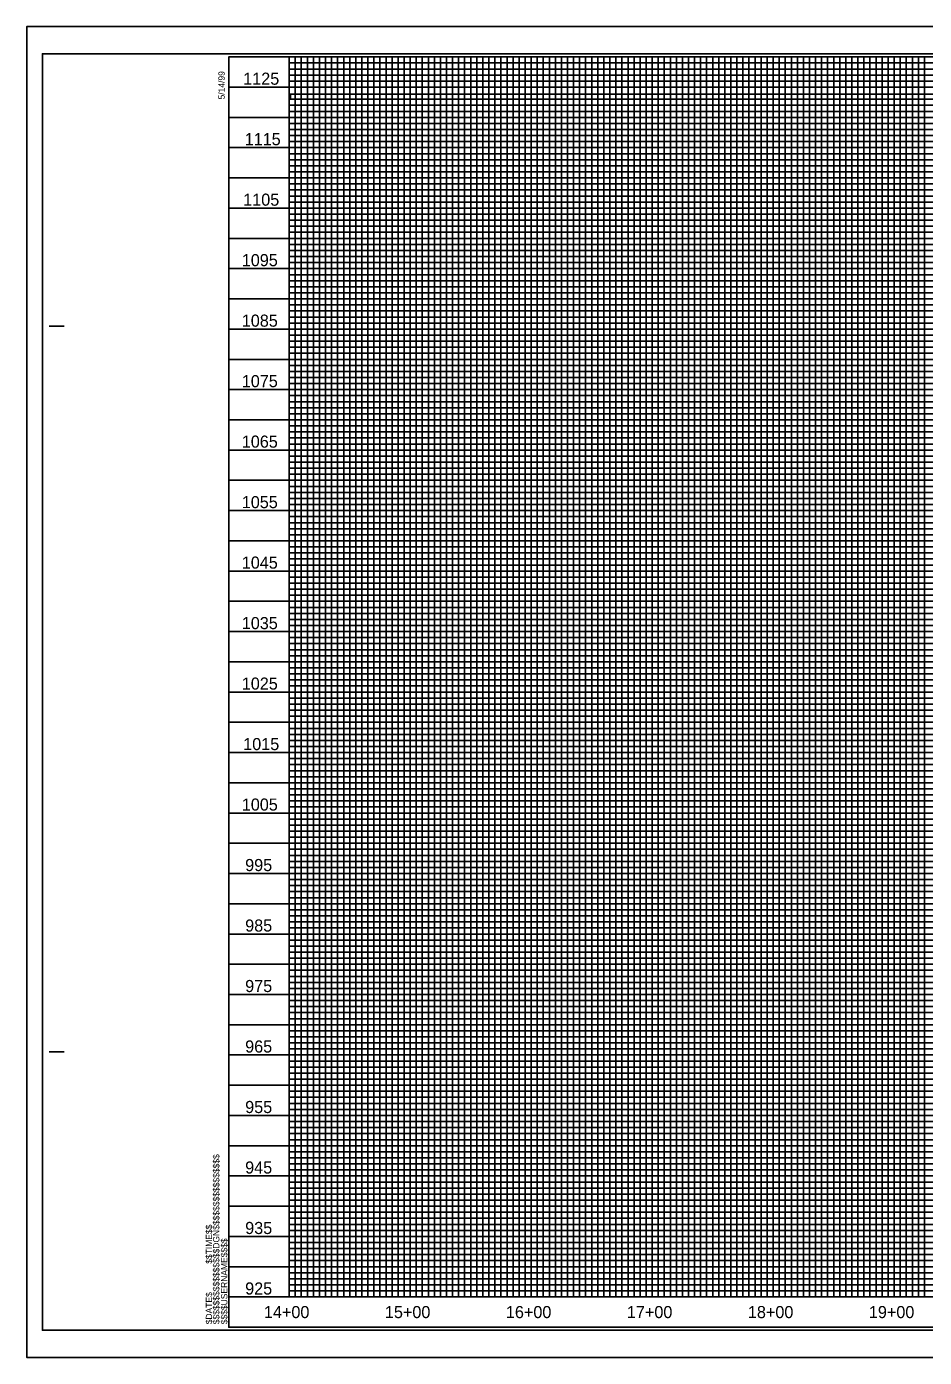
# Model space of a CAD drawing. Extents: x 1260839 to 1262605, y 747346 to 748446.
# Drawn here: x 1260839 to 1261581, y 747346 to 748446 of the extents above; entities that cross this region are included whole.
import ezdxf

# ---------------------------------------------------------------- set-up
doc = ezdxf.new("R2010")
doc.units = 0
for name, color, linetype in [('Pattern 1', 7, 'Continuous'), ('Pattern 2', 7, 'Continuous'), ('Prop Drainage Structure Bridge Opening', 7, 'Continuous'), ('Prop Grid Mask', 7, 'Continuous'), ('Prop Horizontal Alignment Curve and Spiral Data', 7, 'Continuous'), ('Prop Paved Shoulder', 7, 'Continuous'), ('Prop PFL Text', 7, 'Continuous'), ('Prop Roadway Bridge', 7, 'Continuous'), ('Prop Terminator CELL', 7, 'Continuous'), ('Prop Vertical Profile Strip Grade', 7, 'Continuous'), ('Prop VPI Label', 7, 'Continuous'), ('Sheet Sticker Exception Certification CELL', 7, 'Continuous')]:
    doc.layers.add(name, color=color, linetype=linetype)

msp = doc.modelspace()

# ---------------------------------------------------------------- linework, layer by layer
at = {"layer": 'Pattern 1'}
for points in [[(1261005.8, 748420.7), (1261055.8, 748420.7), (1261055.8, 747395.7), (1261105.8, 747395.7), (1261105.8, 748420.7), (1261155.8, 748420.7), (1261155.8, 747395.7), (1261205.8, 747395.7), (1261205.8, 748420.7), (1261255.8, 748420.7), (1261255.8, 747395.7), (1261305.8, 747395.7), (1261305.8, 748420.7), (1261355.8, 748420.7), (1261355.8, 747395.7), (1261405.8, 747395.7), (1261405.8, 748420.7), (1261455.8, 748420.7), (1261455.8, 747395.7), (1261505.8, 747395.7), (1261505.8, 748420.7), (1261555.8, 748420.7), (1261555.8, 747395.7), (1261605.8, 747395.7)], [(1262305.7, 748345.7), (1261005.9, 748345.7), (1261005.9, 748395.7), (1262205.8, 748395.7)], [(1262505.8, 748245.7), (1261005.8, 748245.7), (1261005.8, 748295.7), (1262305.7, 748295.7)], [(1262505.8, 748145.7), (1261005.8, 748145.7), (1261005.8, 748195.7), (1262505.8, 748195.7)], [(1262505.8, 748045.7), (1261005.8, 748045.7), (1261005.8, 748095.7), (1262505.8, 748095.7)], [(1262505.8, 747945.7), (1261005.8, 747945.7), (1261005.8, 747995.7), (1262505.8, 747995.7)], [(1262505.8, 747845.7), (1261005.8, 747845.7), (1261005.8, 747895.7), (1262505.8, 747895.7)], [(1262505.8, 747745.7), (1261005.8, 747745.7), (1261005.8, 747795.7), (1262505.8, 747795.7)], [(1262505.8, 747645.7), (1261005.8, 747645.7), (1261005.8, 747695.7), (1262505.8, 747695.7)], [(1262505.8, 747545.7), (1261005.8, 747545.7), (1261005.8, 747595.7), (1262505.8, 747595.7)], [(1262505.8, 747445.7), (1261005.8, 747445.7), (1261005.8, 747495.7), (1262505.8, 747495.7)]]:
    msp.add_lwpolyline(points, dxfattribs=at)
at = {"layer": 'Pattern 2'}
for points in [[(1261080.8, 747395.7), (1261080.8, 748420.7), (1261130.8, 748420.7), (1261130.8, 747395.7), (1261180.8, 747395.7), (1261180.8, 748420.7), (1261230.8, 748420.7), (1261230.8, 747395.7), (1261280.8, 747395.7), (1261280.8, 748420.7), (1261330.8, 748420.7), (1261330.8, 747395.7), (1261380.8, 747395.7), (1261380.8, 748420.7), (1261430.8, 748420.7), (1261430.8, 747395.7), (1261480.8, 747395.7), (1261480.8, 748420.7), (1261530.8, 748420.7), (1261530.8, 747395.7), (1261580.8, 747395.7), (1261580.8, 748420.7), (1261630.8, 748420.7)], [(1261005.8, 748370.7), (1262305.7, 748370.7)], [(1262305.7, 748320.7), (1261005.8, 748320.7), (1261005.8, 748270.7), (1262305.7, 748270.7)], [(1262505.8, 748220.7), (1261005.8, 748220.7), (1261005.8, 748170.7), (1262505.8, 748170.7)], [(1262505.8, 748120.7), (1261005.8, 748120.7), (1261005.8, 748070.7), (1262505.8, 748070.7)], [(1262505.8, 748020.7), (1261005.8, 748020.7), (1261005.8, 747970.7), (1262505.8, 747970.7)], [(1262505.8, 747920.7), (1261005.8, 747920.7), (1261005.8, 747870.7), (1262505.8, 747870.7)], [(1262505.8, 747820.7), (1261005.8, 747820.7), (1261005.8, 747770.7), (1262505.8, 747770.7)], [(1262505.8, 747720.7), (1261005.8, 747720.7), (1261005.8, 747670.7), (1262505.8, 747670.7)], [(1262505.8, 747620.7), (1261005.8, 747620.7), (1261005.8, 747570.7), (1262505.8, 747570.7)], [(1262505.8, 747520.7), (1261005.8, 747520.7), (1261005.8, 747470.7), (1262505.8, 747470.7)], [(1262505.8, 747420.7), (1261005.8, 747420.7)]]:
    msp.add_lwpolyline(points, dxfattribs=at)
at = {"layer": 'Prop Drainage Structure Bridge Opening'}
for p, q in [((1262522.8, 748445.7), (1260838.8, 748445.7)), ((1260838.8, 748445.7), (1260838.8, 747345.7)), ((1260838.8, 747345.7), (1262522.8, 747345.7))]:
    msp.add_line(p, q, dxfattribs=at)
at = {"layer": 'Prop Grid Mask'}
msp.add_lwpolyline([(1262455.8, 748259.7), (1262455.8, 747395.7), (1261055.8, 747395.7), (1261055.8, 748420.7), (1262305.7, 748420.7), (1262305.7, 748259.7)], close=True, dxfattribs=at)
at = {"layer": 'Prop Paved Shoulder'}
for p, q in [((1260857.3, 748198.2), (1260869.8, 748198.2)), ((1260857.3, 747598.2), (1260869.8, 747598.2)), ((1262505.8, 747395.7), (1261005.8, 747395.7)), ((1261005.8, 747370.7), (1261005.8, 747370.7)), ((1261005.8, 747370.7), (1261005.8, 747370.7)), ((1261005.8, 747370.7), (1261005.8, 747370.7)), ((1261005.8, 747370.7), (1261005.8, 747370.7)), ((1261005.8, 747370.7), (1261005.8, 747370.7)), ((1261005.8, 747370.7), (1261005.8, 747370.7))]:
    msp.add_line(p, q, dxfattribs=at)
msp.add_lwpolyline([(1262505.8, 748420.7), (1261005.8, 748420.7), (1261005.8, 747370.7), (1262505.8, 747370.7)], close=True, dxfattribs=at)
msp.add_lwpolyline([(1261043.3, 747370.7), (1261043.3, 747370.7)], dxfattribs=at)
at = {"layer": 'Prop PFL Text'}
for p, q in [((1261055.8, 748420.7), (1261055.8, 747395.7)), ((1261105.8, 748420.7), (1261105.8, 747395.7)), ((1261155.8, 748420.7), (1261155.8, 747395.7)), ((1261205.8, 748420.7), (1261205.8, 747395.7)), ((1261255.8, 748420.7), (1261255.8, 747395.7)), ((1261305.8, 748420.7), (1261305.8, 747395.7)), ((1261355.8, 748420.7), (1261355.8, 747395.7)), ((1261405.8, 748420.7), (1261405.8, 747395.7)), ((1261455.8, 748420.7), (1261455.8, 747395.7)), ((1261505.8, 748420.7), (1261505.8, 747395.7)), ((1261555.8, 748420.7), (1261555.8, 747395.7)), ((1261005.8, 748395.7), (1262205.8, 748395.7)), ((1261005.8, 748345.7), (1262305.7, 748345.7)), ((1261005.8, 748295.7), (1262305.7, 748295.7)), ((1261005.8, 748245.7), (1262505.8, 748245.7)), ((1261005.8, 748195.7), (1262505.8, 748195.7)), ((1261005.8, 748145.7), (1262505.8, 748145.7)), ((1261005.8, 748095.7), (1262505.8, 748095.7)), ((1261005.8, 748045.7), (1262505.8, 748045.7)), ((1261005.8, 747995.7), (1262505.8, 747995.7)), ((1261005.8, 747945.7), (1262505.8, 747945.7)), ((1261005.8, 747895.7), (1262505.8, 747895.7)), ((1261005.8, 747845.7), (1262505.8, 747845.7)), ((1261005.8, 747795.7), (1262505.8, 747795.7)), ((1261005.8, 747745.7), (1262505.8, 747745.7)), ((1261005.8, 747695.7), (1262505.8, 747695.7)), ((1261005.8, 747645.7), (1262505.8, 747645.7)), ((1261005.8, 747595.7), (1262505.8, 747595.7)), ((1261005.8, 747545.7), (1262505.8, 747545.7)), ((1261005.8, 747495.7), (1262505.8, 747495.7)), ((1261005.8, 747445.7), (1262505.8, 747445.7))]:
    msp.add_line(p, q, dxfattribs=at)
at = {"layer": 'Prop Roadway Bridge'}
msp.add_line((1261005.8, 747370.7), (1261005.8, 747370.7), dxfattribs=at)
at = {"layer": 'Prop Terminator CELL'}
msp.add_lwpolyline([(1262518.3, 748423.3), (1260851.8, 748423.3), (1260851.8, 747368.2), (1262518.3, 747368.2)], close=True, dxfattribs=at)
at = {"layer": 'Prop VPI Label'}
msp.add_lwpolyline([(1262522.8, 748445.7), (1260838.8, 748445.7), (1260838.8, 747345.7), (1262522.8, 747345.7)], close=True, dxfattribs=at)
at = {"layer": 'Sheet Sticker Exception Certification CELL'}
for p, q in [((1262455.8, 748240.7), (1261055.8, 748240.7)), ((1261055.8, 748240.7), (1261055.8, 748235.7)), ((1261055.8, 748235.7), (1262455.8, 748235.7)), ((1262455.8, 748215.7), (1261055.8, 748215.7))]:
    msp.add_line(p, q, dxfattribs=at)
for points in [[(1261060.8, 748420.7), (1261065.8, 748420.7), (1261070.8, 748420.7), (1261075.8, 748420.7), (1261085.8, 748420.7), (1261052.7, 748420.7), (1261057.7, 748420.7), (1261015.8, 748420.7), (1261020.8, 748420.7), (1261025.8, 748420.7), (1261035.8, 748420.7), (1261040.8, 748420.7), (1261045.8, 748420.7), (1261050.8, 748420.7), (1261060.8, 748420.7), (1261060.8, 747395.7), (1261065.8, 747395.7), (1261065.8, 748420.7), (1261070.8, 748420.7), (1261070.8, 747395.7), (1261075.8, 747395.7), (1261075.8, 748420.7), (1261085.8, 748420.7), (1261085.8, 747395.7), (1261090.8, 747395.7), (1261090.8, 748420.7), (1261095.8, 748420.7), (1261095.8, 747395.7), (1261100.8, 747395.7), (1261100.8, 748420.7), (1261110.8, 748420.7), (1261110.8, 747395.7), (1261115.8, 747395.7), (1261115.8, 748420.7), (1261120.8, 748420.7), (1261120.8, 747395.7), (1261125.8, 747395.7), (1261125.8, 748420.7), (1261135.8, 748420.7), (1261135.8, 747395.7), (1261140.8, 747395.7), (1261140.8, 748420.7), (1261145.8, 748420.7), (1261145.8, 747395.7), (1261150.8, 747395.7), (1261150.8, 748420.7), (1261160.8, 748420.7), (1261160.8, 747395.7), (1261165.8, 747395.7), (1261165.8, 748420.7), (1261170.8, 748420.7), (1261170.8, 747395.7), (1261175.8, 747395.7), (1261175.8, 748420.7), (1261185.8, 748420.7), (1261185.8, 747395.7), (1261190.8, 747395.7), (1261190.8, 748420.7), (1261195.8, 748420.7), (1261195.8, 747395.7), (1261200.8, 747395.7), (1261200.8, 748420.7), (1261210.8, 748420.7), (1261210.8, 747395.7), (1261215.8, 747395.7), (1261215.8, 748420.7), (1261220.8, 748420.7), (1261220.8, 747395.7)], [(1261220.8, 747395.7), (1261225.8, 747395.7), (1261225.8, 748420.7), (1261235.8, 748420.7), (1261235.8, 747395.7), (1261240.8, 747395.7), (1261240.8, 748420.7), (1261245.8, 748420.7), (1261245.8, 747395.7), (1261250.8, 747395.7), (1261250.8, 748420.7), (1261260.8, 748420.7), (1261260.8, 747395.7), (1261265.8, 747395.7), (1261265.8, 748420.7), (1261265.8, 748420.7), (1261270.8, 748420.7), (1261270.8, 747395.7), (1261275.8, 747395.7), (1261275.8, 748420.7), (1261285.8, 748420.7), (1261285.8, 747395.7), (1261290.8, 747395.7), (1261290.8, 748420.7), (1261295.8, 748420.7), (1261295.8, 747395.7), (1261300.8, 747395.7), (1261300.8, 748420.7), (1261310.8, 748420.7), (1261310.8, 747395.7), (1261315.8, 747395.7), (1261315.8, 748420.7), (1261320.8, 748420.7), (1261320.8, 747395.7), (1261325.8, 747395.7), (1261325.8, 748420.7), (1261335.8, 748420.7), (1261335.8, 747395.7), (1261340.8, 747395.7), (1261340.8, 748420.7), (1261345.8, 748420.7), (1261345.8, 747395.7), (1261350.8, 747395.7), (1261350.8, 748420.7), (1261360.8, 748420.7), (1261360.8, 747395.7), (1261365.8, 747395.7), (1261365.8, 748420.7), (1261370.8, 748420.7), (1261370.8, 747395.7), (1261375.8, 747395.7), (1261375.8, 748420.7), (1261385.8, 748420.7), (1261385.8, 747395.7), (1261400.8, 747395.7), (1261400.8, 748420.7), (1261410.8, 748420.7), (1261410.8, 747395.7), (1261415.8, 747395.7), (1261415.8, 748420.7), (1261420.8, 748420.7), (1261420.8, 747395.7), (1261425.8, 747395.7), (1261425.8, 748420.7), (1261435.8, 748420.7), (1261435.8, 747395.7), (1261440.8, 747395.7), (1261440.8, 748420.7), (1261445.8, 748420.7), (1261445.8, 747395.7), (1261450.8, 747395.7), (1261450.8, 748420.7), (1261460.8, 748420.7), (1261460.8, 747395.7), (1261465.8, 747395.7), (1261465.8, 748420.7), (1261470.8, 748420.7), (1261470.8, 747395.7), (1261475.8, 747395.7), (1261475.8, 748420.7), (1261485.8, 748420.7), (1261485.8, 747395.7), (1261490.8, 747395.7), (1261490.8, 748420.7), (1261495.8, 748420.7), (1261495.8, 747395.7), (1261500.8, 747395.7), (1261500.8, 748420.7), (1261510.8, 748420.7), (1261510.8, 747395.7), (1261515.8, 747395.7), (1261515.8, 748420.7), (1261520.8, 748420.7), (1261520.8, 747395.7), (1261525.8, 747395.7), (1261525.8, 748420.7), (1261535.8, 748420.7), (1261535.8, 747395.7)], [(1261390.8, 748420.7), (1261390.8, 747395.7), (1261395.8, 747395.7), (1261395.8, 748420.7)], [(1261390.8, 748420.1), (1261390.8, 747395.7), (1261395.8, 747395.7), (1261395.8, 748420.1)], [(1261540.8, 748420.7), (1261540.8, 747395.7), (1261545.8, 747395.7), (1261545.8, 748420.7), (1261550.8, 748420.7), (1261550.8, 747395.7), (1261560.8, 747395.7), (1261560.8, 748420.7), (1261565.8, 748420.7), (1261565.8, 747395.7), (1261570.8, 747395.7), (1261570.8, 748420.7), (1261575.8, 748420.7), (1261575.8, 747395.7)], [(1262205.8, 748415.7), (1261055.8, 748415.7), (1261055.8, 748410.7), (1262205.8, 748410.7)], [(1262205.8, 748405.7), (1261055.8, 748405.7), (1261055.8, 748400.7), (1262205.8, 748400.7)], [(1262205.8, 748390), (1261056.8, 748390), (1261056.8, 748385.7), (1262205.8, 748385.7)], [(1262205.8, 748380.7), (1261055.8, 748380.7), (1261055.8, 748375.7), (1262205.8, 748375.7)], [(1262305.7, 748365.7), (1261055.8, 748365.7), (1261055.8, 748360.7), (1262305.7, 748360.7)], [(1262305.7, 748355.7), (1261055.8, 748355.7), (1261055.8, 748350.7), (1262305.7, 748350.7)], [(1262305.7, 748340.7), (1261055.8, 748340.7), (1261055.8, 748335.7), (1262305.7, 748335.7)], [(1262305.7, 748330.7), (1261055.8, 748330.7), (1261055.8, 748325.7), (1262305.7, 748325.7)], [(1262305.7, 748315.7), (1261055.8, 748315.7), (1261055.8, 748310.7), (1262305.7, 748310.7)], [(1262305.7, 748305.7), (1261055.8, 748305.7), (1261055.8, 748300.7), (1262305.7, 748300.7)], [(1262305.7, 748290.7), (1261055.8, 748290.7), (1261055.8, 748285.7), (1262305.7, 748285.7)], [(1262305.7, 748280.7), (1261055.8, 748280.7), (1261055.8, 748280.7), (1261055.8, 748260.7), (1262305.7, 748260.7)], [(1261055.8, 748275.7), (1262305.7, 748275.7)], [(1262305.7, 748265.7), (1261055.8, 748265.7)], [(1262455.8, 748255.7), (1261055.8, 748255.7), (1261055.8, 748250.7), (1262455.8, 748250.7)], [(1262455.8, 748230.7), (1261055.8, 748230.7), (1261055.8, 748225.7), (1262455.8, 748225.7)], [(1262455.8, 748210.7), (1261055.8, 748210.7), (1261055.8, 748205.7), (1262455.8, 748205.7)], [(1262455.8, 748200.7), (1261055.8, 748200.7)], [(1261055.8, 748190.7), (1262455.8, 748190.7)], [(1262455.8, 748185.7), (1261055.8, 748185.7), (1261055.8, 748180.7), (1262455.8, 748180.7)], [(1262455.8, 748175.7), (1261055.8, 748175.7), (1261055.8, 748165.7), (1262455.8, 748165.7)], [(1262455.8, 748160.7), (1261055.8, 748160.7), (1261055.8, 748155.7), (1262455.8, 748155.7)], [(1262455.8, 748150.7), (1261055.8, 748150.7), (1261055.8, 748140.7), (1262455.8, 748140.7)], [(1262455.8, 748135.7), (1261055.8, 748135.7), (1261055.8, 748130.7), (1262455.8, 748130.7)], [(1262455.8, 748125.7), (1261055.8, 748125.7), (1261055.8, 748115.7), (1262455.8, 748115.7)], [(1262455.8, 748110.7), (1261055.8, 748110.7), (1261055.8, 748105.7), (1262455.8, 748105.7)], [(1262455.8, 748100.7), (1261055.8, 748100.7), (1261055.8, 748090.7), (1262455.8, 748090.7)], [(1262455.8, 748085.7), (1261055.8, 748085.7), (1261055.8, 748080.7), (1262455.8, 748080.7)], [(1262455.8, 748075.7), (1261055.8, 748075.7), (1261055.8, 748065.7), (1262455.8, 748065.7)], [(1262455.8, 748060.7), (1261055.8, 748060.7), (1261055.8, 748055.7), (1262455.8, 748055.7)], [(1262455.8, 748050.7), (1261055.8, 748050.7), (1261055.8, 748040.7), (1262455.8, 748040.7)], [(1262455.8, 748035.7), (1261055.8, 748035.7), (1261055.8, 748030.7), (1262455.8, 748030.7)], [(1262455.8, 748025.7), (1261055.8, 748025.7), (1261055.8, 748015.7), (1262455.8, 748015.7)], [(1262455.8, 748010.7), (1261055.8, 748010.7), (1261055.8, 748005.7), (1262455.8, 748005.7)], [(1262455.8, 748000.7), (1261055.8, 748000.7), (1261055.8, 747990.7), (1262455.8, 747990.7)], [(1262455.8, 747985.7), (1261055.8, 747985.7), (1261055.8, 747980.7), (1262455.8, 747980.7)], [(1262455.8, 747975.7), (1261055.8, 747975.7), (1261055.8, 747965.7), (1262455.8, 747965.7)], [(1262455.8, 747960.7), (1261055.8, 747960.7), (1261055.8, 747955.7), (1262455.8, 747955.7)], [(1262455.8, 747950.7), (1261055.8, 747950.7), (1261055.8, 747940.7), (1262455.8, 747940.7)], [(1262455.8, 747935.7), (1261055.8, 747935.7), (1261055.8, 747930.7), (1262455.8, 747930.7)], [(1262455.8, 747925.7), (1261055.8, 747925.7), (1261055.8, 747915.7), (1262455.8, 747915.7)], [(1262455.8, 747910.7), (1261055.8, 747910.7), (1261055.8, 747905.7), (1262455.8, 747905.7)], [(1262455.8, 747900.7), (1261055.8, 747900.7)], [(1261055.8, 747890.7), (1262455.8, 747890.7)], [(1262455.8, 747885.7), (1261055.8, 747885.7), (1261055.8, 747880.7), (1262455.8, 747880.7)], [(1262455.8, 747875.7), (1261055.8, 747875.7), (1261055.8, 747865.7), (1262455.8, 747865.7)], [(1262455.8, 747860.7), (1261055.8, 747860.7), (1261055.8, 747855.7), (1262455.8, 747855.7)], [(1262455.8, 747850.7), (1261055.8, 747850.7), (1261055.8, 747840.7), (1262455.8, 747840.7)], [(1262455.8, 747835.7), (1261055.8, 747835.7), (1261055.8, 747830.7), (1262455.8, 747830.7)], [(1262455.8, 747825.7), (1261055.8, 747825.7), (1261055.8, 747815.7), (1262455.8, 747815.7)], [(1262455.8, 747810.7), (1261055.8, 747810.7), (1261055.8, 747805.7), (1262455.8, 747805.7)], [(1262455.8, 747800.7), (1261055.8, 747800.7), (1261055.8, 747790.7), (1262455.8, 747790.7)], [(1262455.8, 747785.7), (1261055.8, 747785.7), (1261055.8, 747780.7), (1262455.8, 747780.7)], [(1262455.8, 747775.7), (1261055.8, 747775.7), (1261055.8, 747765.7), (1262455.8, 747765.7)], [(1262455.8, 747760.7), (1261055.8, 747760.7), (1261055.8, 747755.7), (1262455.8, 747755.7)], [(1262455.8, 747750.7), (1261055.8, 747750.7), (1261055.8, 747740.7), (1262455.8, 747740.7)], [(1262455.8, 747735.7), (1261055.8, 747735.7), (1261055.8, 747730.7), (1262455.8, 747730.7)], [(1262455.8, 747725.7), (1261055.8, 747725.7), (1261055.8, 747715.7), (1262455.8, 747715.7)], [(1262455.8, 747710.7), (1261055.8, 747710.7), (1261055.8, 747705.7), (1262455.8, 747705.7)], [(1262455.8, 747700.7), (1261055.8, 747700.7), (1261055.8, 747690.7), (1262455.8, 747690.7)], [(1262455.8, 747685.7), (1261055.8, 747685.7), (1261055.8, 747680.7), (1262455.8, 747680.7)], [(1262455.8, 747675.7), (1261055.8, 747675.7), (1261055.8, 747665.7), (1262455.8, 747665.7)], [(1262455.8, 747660.7), (1261055.8, 747660.7), (1261055.8, 747655.7), (1262455.8, 747655.7)], [(1262455.8, 747650.7), (1261055.8, 747650.7), (1261055.8, 747640.7), (1262455.8, 747640.7)], [(1262455.8, 747635.7), (1261055.8, 747635.7), (1261055.8, 747630.7), (1262455.8, 747630.7)], [(1262455.8, 747625.7), (1261055.8, 747625.7), (1261055.8, 747615.7), (1262455.8, 747615.7)], [(1262455.8, 747610.7), (1261055.8, 747610.7), (1261055.8, 747605.7), (1262455.8, 747605.7)], [(1262455.8, 747600.7), (1261055.8, 747600.7)], [(1261055.8, 747590.7), (1262455.8, 747590.7)], [(1262455.8, 747585.7), (1261055.8, 747585.7), (1261055.8, 747580.7), (1262455.8, 747580.7)], [(1262455.8, 747575.7), (1261055.8, 747575.7)], [(1261055.8, 747565.7), (1262455.8, 747565.7)], [(1262455.8, 747560.7), (1261055.8, 747560.7), (1261055.8, 747555.7), (1262455.8, 747555.7)], [(1262455.8, 747550.7), (1261055.8, 747550.7), (1261055.8, 747540.7), (1262455.8, 747540.7)], [(1262455.8, 747535.7), (1261055.8, 747535.7), (1261055.8, 747530.7), (1262455.8, 747530.7)], [(1262455.8, 747525.7), (1261055.8, 747525.7), (1261055.8, 747515.7), (1262455.8, 747515.7)], [(1262455.8, 747510.7), (1261055.8, 747510.7), (1261055.8, 747505.7), (1262455.8, 747505.7)], [(1262455.8, 747500.7), (1261055.8, 747500.7), (1261055.8, 747490.7), (1262455.8, 747490.7)], [(1262455.8, 747485.7), (1261055.8, 747485.7), (1261055.8, 747480.7), (1262455.8, 747480.7)], [(1262455.8, 747475.7), (1261055.8, 747475.7), (1261055.8, 747465.7), (1262455.8, 747465.7)], [(1262455.8, 747460.7), (1261055.8, 747460.7), (1261055.8, 747455.7), (1262455.8, 747455.7)], [(1262455.8, 747450.7), (1261055.8, 747450.7), (1261055.8, 747440.7), (1262455.8, 747440.7)], [(1262455.8, 747435.7), (1261055.8, 747435.7), (1261055.8, 747430.7), (1262455.8, 747430.7)], [(1262455.8, 747425.7), (1261055.8, 747425.7), (1261055.8, 747415.7), (1262455.8, 747415.7)], [(1262455.8, 747410.7), (1261055.8, 747410.7), (1261055.8, 747405.7), (1262455.8, 747405.7)], [(1262455.8, 747400.7), (1261055.8, 747400.7)]]:
    msp.add_lwpolyline(points, dxfattribs=at)

# ---------------------------------------------------------------- texts
at = {"layer": 'Prop Horizontal Alignment Curve and Spiral Data'}
for s, p in [('14+00', (1261034.9, 747378.2)), ('15+00', (1261134.9, 747378.2)), ('16+00', (1261234.9, 747378.2)), ('17+00', (1261334.9, 747378.2)), ('18+00', (1261434.9, 747378.2)), ('19+00', (1261534.9, 747378.2))]:
    msp.add_text(s, height=10, dxfattribs=at).set_placement(p)
at = {"layer": 'Prop Paved Shoulder'}
msp.add_text('5/14/99', height=5.25, rotation=90, dxfattribs=at).set_placement((1261002.5, 748385.5))
at = {"layer": 'Prop Roadway Bridge'}
for s, p in [('$$$$$$$$$$$$$$$$DGN$$$$$$$$$$$$$$$$', (1260998.1, 747373.1)), ('$$TIME$$', (1260992.1, 747423.1)), ('$$$$USERNAME$$$$', (1261004.7, 747373.1)), ('$DATE$', (1260992.1, 747373.1))]:
    msp.add_text(s, height=5.25, rotation=90, dxfattribs=at).set_placement(p)
at = {"layer": 'Prop Vertical Profile Strip Grade'}
for s, p in [('1125', (1261017.8, 748397.7)), ('1115', (1261019, 748347.7)), ('1105', (1261017.8, 748297.7)), ('1095', (1261016.6, 748247.7)), ('1085', (1261016.6, 748197.7)), ('1075', (1261016.6, 748147.7)), ('1065', (1261016.6, 748097.7)), ('1055', (1261016.6, 748047.7)), ('1045', (1261016.6, 747997.7)), ('1035', (1261016.6, 747947.7)), ('1025', (1261016.6, 747897.7)), ('1015', (1261017.8, 747847.7)), ('1005', (1261016.6, 747797.7)), ('995', (1261019.4, 747747.7)), ('985', (1261019.4, 747697.7)), ('975', (1261019.4, 747647.7)), ('965', (1261019.4, 747597.7)), ('955', (1261019.4, 747547.7)), ('945', (1261019.4, 747497.7)), ('935', (1261019.4, 747447.7)), ('925', (1261019.4, 747397.7))]:
    msp.add_text(s, height=10, dxfattribs=at).set_placement(p)

doc.saveas('drawing.dxf')
